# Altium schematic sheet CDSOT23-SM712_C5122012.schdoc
size 127 x 101 mm
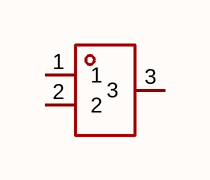
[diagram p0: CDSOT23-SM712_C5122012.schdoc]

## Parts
U?  cdsot23-sm712_c5122012  [SOT-23-3_L2.9-W1.3-P0.95-LS2.4-BR]  (value not drawn)

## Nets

Not connected (* = marked no-connect by the designer): U? 1 2 3

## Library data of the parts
U? = cdsot23-sm712_c5122012: 极性:双向;反向截止电压(Vrwm):12V；7V;钳位电压:12V；26V;峰值脉冲电流(Ipp):17A;峰值脉冲功率(Ppp):400W;击穿电压:7.5V；13.3V;; Manufacturer: TECH PUBLIC(台舟); AddInBom: yes; ModelId: c62791f0466c4ae2a892c056b845b0ca; ModelName: SOT-23-3P_L2.9-W1.3-H1.0-LS2.4-P0.95; ModelTransform: 98.425,114.173,0,180,0,0,0.0005,-0.0005,0; Polarity: 双向; Reverse Stand-Off Voltage (Vrwm): 12V；7V; Peak Pulse Current (Ipp): 17A; Peak Pulse Power Dissipation (Ppp): 400W; Reverse Leakage Current (Ir): 50nA；2uA; Number of Channels: 双路; level of protection: IEC 61000-4-2；IEC 61000-4-4；IEC 61000-4-5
